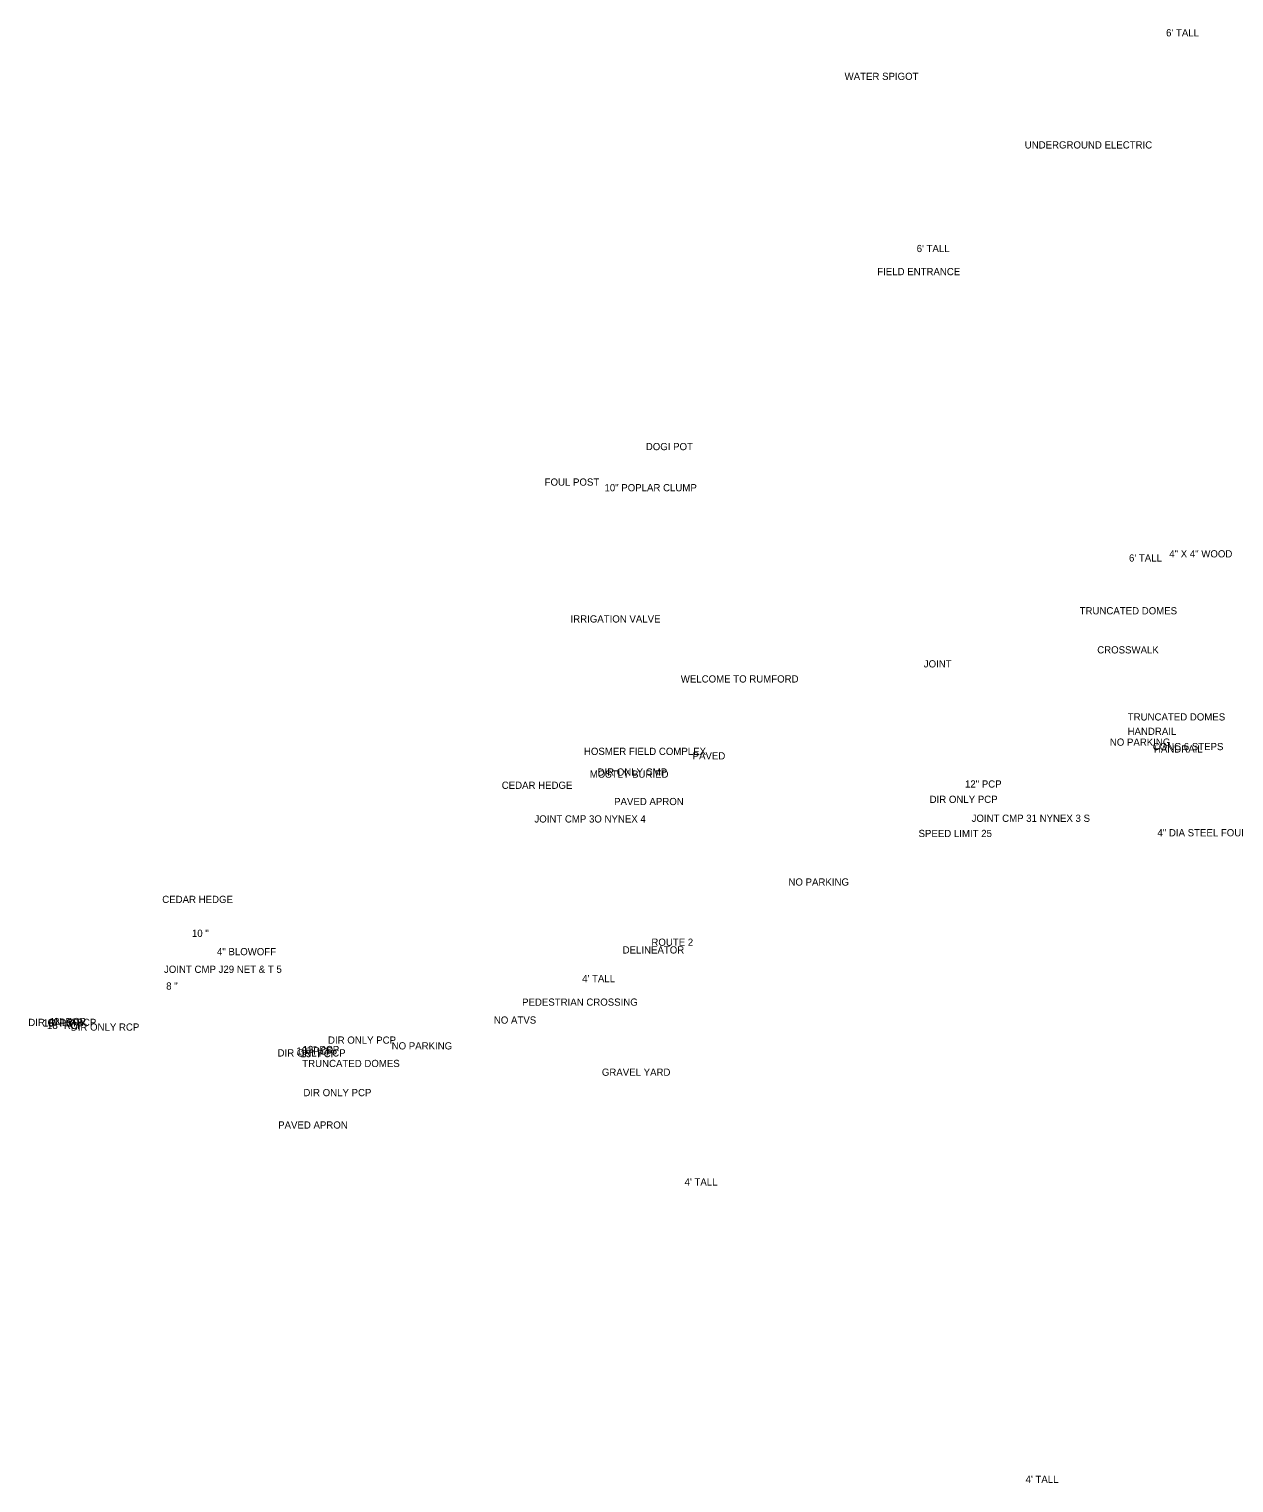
# Model space of a CAD drawing. Extents: x 939002 to 940105, y 627262 to 628202.
# Drawn here: x 939002 to 939420, y 627352 to 627856 of the extents above; entities that cross this region are included whole.
import ezdxf

# ---------------------------------------------------------------- set-up
doc = ezdxf.new("R2010")
doc.units = 0
for name, color, linetype in [('S_Annotation_Label', 7, 'Continuous'), ('S_Buildings_Steps_Brick', 7, 'Continuous'), ('S_Drainage_Culvert_Top', 7, 'Continuous'), ('S_Drainage_Invert', 7, 'Continuous'), ('S_Fencing_ChainLink', 7, 'Continuous'), ('S_Misc_MiscFeature', 7, 'Continuous'), ('S_Roadway_Drive_Gravel', 7, 'Continuous'), ('S_Roadway_Drive_Paved', 7, 'Continuous'), ('S_Roadway_Entr_Field_Wood', 7, 'Continuous'), ('S_Roadway_Sidewalks', 7, 'Continuous'), ('S_Traffic_Post_Conc', 7, 'Continuous'), ('S_Traffic_Sign_DoublePost', 7, 'Continuous'), ('S_Traffic_Sign_SinglePost', 7, 'Continuous'), ('S_Trees_Decid_NonPay', 7, 'Continuous'), ('S_Trees_TreeLine', 7, 'Continuous'), ('S_Utilities_Pole_Power', 7, 'Continuous'), ('S_Utilities_Pole_Support3', 7, 'Continuous'), ('S_Utilities_UG_Water_Gate', 7, 'Continuous'), ('S_Utilities_UG_Water_Line', 7, 'Continuous')]:
    doc.layers.add(name, color=color, linetype=linetype)

msp = doc.modelspace()

# ---------------------------------------------------------------- texts
at = {"layer": 'S_Annotation_Label'}
for s, height, p in [('TRUNCATED DOMES', 2.4999, (939366.77, 627652.95)), ('CROSSWALK', 2.5, (939372.87, 627639.39)), ('TRUNCATED DOMES', 2.4999, (939383.46, 627616.13)), ('TRUNCATED DOMES', 2.4999, (939097.11, 627495.89))]:
    msp.add_text(s, height=height, dxfattribs=at).set_placement(p)
at = {"layer": 'S_Buildings_Steps_Brick'}
msp.add_text('CONC 6 STEPS', height=2.4999, dxfattribs=at).set_placement((939392.13, 627605.84))
at = {"layer": 'S_Drainage_Culvert_Top'}
for s, height, p in [('MOSTLY BURIED', 2.4999, (939196.84, 627596.28)), ('DIR ONLY CMP', 2.4999, (939199.53, 627597)), ('12" PCP', 2.5, (939327, 627592.84)), ('DIR ONLY PCP', 2.4999, (939314.73, 627587.53)), ('DIR ONLY PCP', 2.4999, (939002.07, 627510.14)), ('18" PCP', 2.5, (939007.13, 627509.93)), ('18" RCP', 2.5, (939008.55, 627509.11)), ('42" RCP', 2.5, (939009.16, 627510.43)), ('DIR ONLY RCP', 2.4999, (939016.81, 627508.52)), ('DIR ONLY PCP', 2.4999, (939106.04, 627504)), ('DIR ONLY PCP', 2.4999, (939088.55, 627499.55)), ('18" PCP', 2.5, (939095.08, 627500.23)), ('15" PCP', 2.5, (939096.5, 627499.33)), ('12" PCP', 2.5, (939097.22, 627500.73)), ('DIR ONLY PCP', 2.4999, (939097.5, 627485.78))]:
    msp.add_text(s, height=height, dxfattribs=at).set_placement(p)
at = {"layer": 'S_Drainage_Invert'}
for s, p in [('12" PCP', (939326.99, 627592.85)), ('18" PCP', (939007.15, 627510)), ('18" PCP', (939008.58, 627509.09)), ('42" RCP', (939009.14, 627510.44)), ('18" PCP', (939095.12, 627500.23)), ('15" PCP', (939096.49, 627499.31)), ('12" PCP', (939097.21, 627500.73))]:
    msp.add_text(s, height=2.5, dxfattribs=at).set_placement(p)
at = {"layer": 'S_Fencing_ChainLink'}
for s, p in [("6' TALL", (939396.76, 627853.48)), ("6' TALL", (939310.24, 627778.63)), ("6' TALL", (939383.89, 627671.27)), ("4' TALL", (939194.2, 627525.33)), ("4' TALL", (939229.73, 627454.77)), ("4' TALL", (939348.02, 627351.6))]:
    msp.add_text(s, height=2.5, dxfattribs=at).set_placement(p)
at = {"layer": 'S_Misc_MiscFeature'}
for p in [(939383.4, 627611.13), (939392.55, 627604.99)]:
    msp.add_text('HANDRAIL', height=2.5, dxfattribs=at).set_placement(p)
at = {"layer": 'S_Roadway_Drive_Gravel'}
msp.add_text('GRAVEL YARD', height=2.4999, dxfattribs=at).set_placement((939201.04, 627492.86))
at = {"layer": 'S_Roadway_Drive_Paved'}
for p in [(939205.28, 627586.77), (939088.74, 627474.54)]:
    msp.add_text('PAVED APRON', height=2.4999, dxfattribs=at).set_placement(p)
at = {"layer": 'S_Roadway_Entr_Field_Wood'}
msp.add_text('FIELD ENTRANCE', height=2.4999, dxfattribs=at).set_placement((939296.56, 627770.62))
at = {"layer": 'S_Roadway_Sidewalks'}
msp.add_text('PAVED', height=2.5, dxfattribs=at).set_placement((939232.52, 627602.61))
at = {"layer": 'S_Traffic_Post_Conc'}
for s, height, p in [('WATER SPIGOT', 2.4999, (939285.24, 627838.37)), ('FOUL POST', 2.5, (939181.18, 627697.6)), ('4" X 4" WOOD', 2.4999, (939397.86, 627672.71)), ('4" DIA STEEL FOUL POST', 2.4999, (939393.77, 627575.94))]:
    msp.add_text(s, height=height, dxfattribs=at).set_placement(p)
at = {"layer": 'S_Traffic_Sign_DoublePost'}
for s, p in [('WELCOME TO RUMFORD', (939228.41, 627629.3)), ('HOSMER FIELD COMPLEX', (939194.81, 627604.18))]:
    msp.add_text(s, height=2.4999, dxfattribs=at).set_placement(p)
at = {"layer": 'S_Traffic_Sign_SinglePost'}
for s, height, p in [('UNDERGROUND ELECTRIC', 2.4999, (939347.73, 627814.58)), ('DOGI POT', 2.5, (939216.28, 627709.92)), ('NO PARKING', 2.5, (939377.25, 627607.37)), ('SPEED LIMIT 25', 2.4999, (939310.89, 627575.69)), ('NO PARKING', 2.5, (939265.76, 627558.84)), ('DELINEATOR', 2.5, (939208.24, 627535.28)), ('ROUTE 2', 2.5, (939218.22, 627537.96)), ('PEDESTRIAN CROSSING', 2.4999, (939173.36, 627517.17)), ('NO ATVS', 2.5, (939163.57, 627510.95)), ('NO PARKING', 2.5, (939128.11, 627502))]:
    msp.add_text(s, height=height, dxfattribs=at).set_placement(p)
at = {"layer": 'S_Trees_Decid_NonPay'}
msp.add_text('10" POPLAR CLUMP', height=2.4999, dxfattribs=at).set_placement((939201.94, 627695.65))
at = {"layer": 'S_Trees_TreeLine'}
for p in [(939166.3, 627592.41), (939048.54, 627552.82)]:
    msp.add_text('CEDAR HEDGE', height=2.4999, dxfattribs=at).set_placement(p)
at = {"layer": 'S_Utilities_Pole_Power'}
for s, height, p in [('JOINT', 2.5, (939312.71, 627634.54)), ('JOINT CMP 3O NYNEX 4', 2.4999, (939177.63, 627580.73)), ('JOINT CMP J29 NET & T 5', 2.4999, (939049.14, 627528.57))]:
    msp.add_text(s, height=height, dxfattribs=at).set_placement(p)
at = {"layer": 'S_Utilities_Pole_Support3'}
msp.add_text('JOINT CMP 31 NYNEX 3 S', height=2.4999, dxfattribs=at).set_placement((939329.3, 627580.96))
at = {"layer": 'S_Utilities_UG_Water_Gate'}
msp.add_text('IRRIGATION VALVE', height=2.4999, dxfattribs=at).set_placement((939190.17, 627650.12))
at = {"layer": 'S_Utilities_UG_Water_Line'}
for s, p in [('10 "', (939058.83, 627541.06)), ('4" BLOWOFF', (939067.52, 627534.68)), ('8 "', (939049.9, 627522.76))]:
    msp.add_text(s, height=2.5, dxfattribs=at).set_placement(p)

doc.saveas('drawing.dxf')
